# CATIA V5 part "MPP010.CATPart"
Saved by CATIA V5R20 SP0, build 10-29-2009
Part number: MPP010
Definition: NONE
Nomenclature: MPP010
Source: Unknown
Description: MPP010
Bounding box of the stored display mesh (mm): x 0 to 12, y -5 to 5, z -5 to 5
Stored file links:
  C:\Users\Utente\Desktop\IO LAVORO\3D X SITO CF\X SITO\PLASTICA\CFMR\MPP010.CATPart
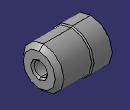
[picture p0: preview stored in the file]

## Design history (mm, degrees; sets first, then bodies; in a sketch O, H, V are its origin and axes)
Body1 "MPP010" (main body)
  Solid1: solid without history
